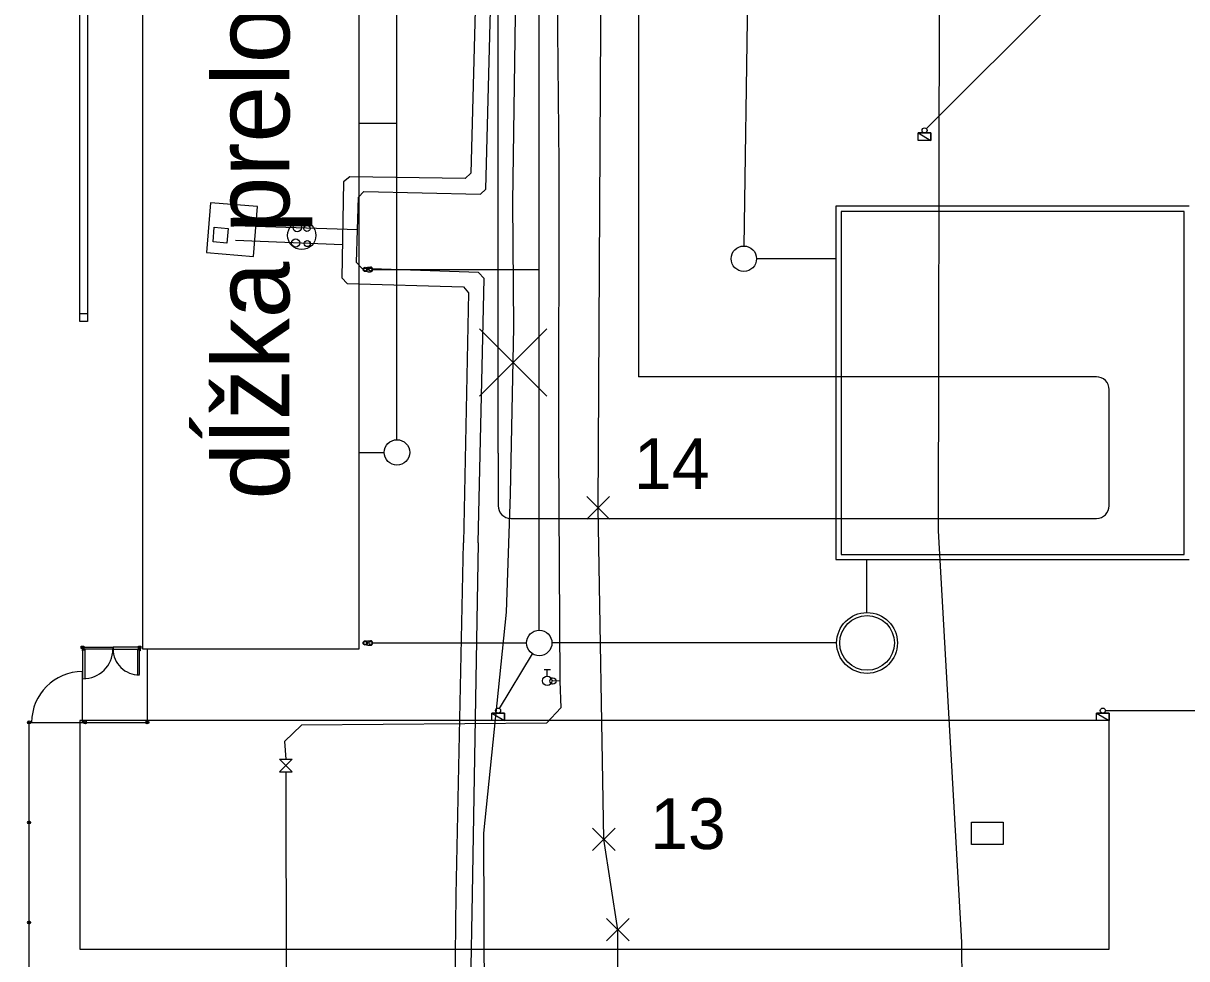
# Model space of a CAD drawing. Extents: x -264095 to -263675, y -1242370 to -1242073.
# Drawn here: x -263972.3 to -263926.53, y -1242264.36 to -1242227.54 of the extents above; entities that cross this region are included whole.
import ezdxf

# ---------------------------------------------------------------- set-up
doc = ezdxf.new("R2010")
doc.units = 0
for name, color, linetype in [('BODY', 7, 'Continuous'), ('KFA_2D_JESTVUJUCE_IS_DSP', 7, 'Continuous'), ('KFA_2D_SITUACIA_DSP', 7, 'Continuous'), ('ORANGE_KABEL_NOVA_TRASA', 7, 'Continuous'), ('POPIS', 7, 'Continuous'), ('Pripojka_NN_pre_ORANGE_vysielac_povodna_trasa', 7, 'Continuous')]:
    doc.layers.add(name, color=color, linetype=linetype)

msp = doc.modelspace()

# ---------------------------------------------------------------- linework, layer by layer
at = {"layer": 'BODY'}
for p, q in [((-263950.126, -1242247.056), (-263949.242, -1242246.172)), ((-263949.242, -1242247.056), (-263950.126, -1242246.172)), ((-263949.901, -1242260.101), (-263949.017, -1242259.217)), ((-263949.017, -1242260.101), (-263949.901, -1242259.217)), ((-263949.352, -1242263.66), (-263948.468, -1242262.776)), ((-263948.468, -1242263.66), (-263949.352, -1242262.776))]:
    msp.add_line(p, q, dxfattribs=at)
at = {"layer": 'KFA_2D_JESTVUJUCE_IS_DSP'}
for p, q in [((-263943.946, -1242236.311), (-263943.136, -1242185.245)), ((-263936.242, -1242215.207), (-263936.305, -1242247.518)), ((-263951.356, -1242221.201), (-263951.228, -1242233.09)), ((-263954.451, -1242224.536), (-263954.692, -1242233.447)), ((-263954.106, -1242234.073), (-263953.851, -1242224.476)), ((-263951.228, -1242233.09), (-263951.241, -1242244.319)), ((-263954.692, -1242233.447), (-263954.912, -1242233.658)), ((-263959.696, -1242233.784), (-263959.771, -1242237.559)), ((-263959.451, -1242233.59), (-263959.696, -1242233.784)), ((-263954.912, -1242233.658), (-263959.451, -1242233.59)), ((-263959.189, -1242236.963), (-263959.11, -1242234.394)), ((-263959.11, -1242234.394), (-263958.895, -1242234.164)), ((-263958.895, -1242234.164), (-263954.308, -1242234.275)), ((-263954.308, -1242234.275), (-263954.106, -1242234.073)), ((-263964.927, -1242234.61), (-263965.088, -1242236.571)), ((-263963.078, -1242234.762), (-263964.927, -1242234.61)), ((-263963.239, -1242236.723), (-263963.078, -1242234.762)), ((-263964.833, -1242236.15), (-263964.786, -1242235.573)), ((-263964.786, -1242235.573), (-263964.238, -1242235.618)), ((-263964.238, -1242235.618), (-263964.285, -1242236.195)), ((-263959.149, -1242235.676), (-263963.972, -1242235.519)), ((-263964.285, -1242236.195), (-263964.833, -1242236.15)), ((-263959.745, -1242236.267), (-263963.952, -1242236.1)), ((-263965.088, -1242236.571), (-263963.239, -1242236.723)), ((-263958.966, -1242237.191), (-263959.189, -1242236.963)), ((-263954.387, -1242237.352), (-263958.966, -1242237.191)), ((-263959.771, -1242237.559), (-263959.557, -1242237.791)), ((-263954.408, -1242247.997), (-263954.173, -1242237.595)), ((-263954.173, -1242237.595), (-263954.387, -1242237.352)), ((-263959.557, -1242237.791), (-263954.983, -1242237.917)), ((-263954.983, -1242237.917), (-263954.788, -1242238.153)), ((-263954.788, -1242238.153), (-263954.978, -1242247.991)), ((-263951.241, -1242244.319), (-263951.192, -1242253.436)), ((-263936.305, -1242247.518), (-263935.392, -1242263.705)), ((-263955.264, -1242261.849), (-263954.978, -1242247.991)), ((-263954.408, -1242247.997), (-263954.644, -1242261.82)), ((-263951.562, -1242252.985), (-263951.812, -1242252.985)), ((-263951.687, -1242253.235), (-263951.687, -1242252.985)), ((-263951.192, -1242253.436), (-263951.461, -1242253.427)), ((-263951.192, -1242253.436), (-263951.15, -1242254.486)), ((-263951.15, -1242254.486), (-263951.718, -1242255.083)), ((-263961.355, -1242255.168), (-263962.028, -1242255.805)), ((-263951.718, -1242255.083), (-263961.355, -1242255.168)), ((-263962.028, -1242255.805), (-263961.971, -1242256.501)), ((-263962.221, -1242256.501), (-263961.721, -1242256.501)), ((-263961.721, -1242256.501), (-263962.221, -1242257.001)), ((-263961.721, -1242257.001), (-263962.221, -1242256.501)), ((-263962.221, -1242257.001), (-263961.721, -1242257.001)), ((-263961.971, -1242257.001), (-263961.846, -1242321.299)), ((-263934.994, -1242258.986), (-263933.751, -1242258.986)), ((-263934.994, -1242259.867), (-263934.994, -1242258.986)), ((-263933.751, -1242258.986), (-263933.751, -1242259.867)), ((-263933.751, -1242259.867), (-263934.994, -1242259.867)), ((-263955.442, -1242275.089), (-263955.264, -1242261.849)), ((-263954.644, -1242261.82), (-263954.858, -1242275.059)), ((-263935.392, -1242263.705), (-263934.919, -1242303.408))]:
    msp.add_line(p, q, dxfattribs=at)
for centre, radius in [((-263961.345, -1242235.895), 0.556), ((-263961.522, -1242235.583), 0.164), ((-263961.138, -1242235.62), 0.122), ((-263961.583, -1242236.191), 0.164), ((-263961.128, -1242236.214), 0.122), ((-263951.687, -1242253.423), 0.188), ((-263951.461, -1242253.427), 0.125)]:
    msp.add_circle(centre, radius, dxfattribs=at)
at = {"layer": 'KFA_2D_SITUACIA_DSP'}
for p, q in [((-263948.093, -1242087.901), (-263948.093, -1242241.458)), ((-263953.617, -1242244.458), (-263953.617, -1242093.307)), ((-263957.597, -1242243.932), (-263957.597, -1242193.383)), ((-263967.593, -1242252.182), (-263967.593, -1242197.782)), ((-263967.593, -1242252.182), (-263967.593, -1242197.782)), ((-263959.097, -1242197.782), (-263959.093, -1242252.182)), ((-263959.093, -1242197.782), (-263959.093, -1242252.182)), ((-263970.07, -1242239.282), (-263970.071, -1242210.684)), ((-263969.77, -1242210.682), (-263969.77, -1242239.282)), ((-263936.772, -1242231.691), (-263926.947, -1242221.865)), ((-263952, -1242251.432), (-263952, -1242223.527)), ((-263959.097, -1242231.482), (-263957.597, -1242231.482)), ((-263937.093, -1242231.862), (-263936.593, -1242231.862)), ((-263937.093, -1242232.152), (-263937.093, -1242231.862)), ((-263937.093, -1242231.862), (-263936.593, -1242232.152)), ((-263937.093, -1242231.862), (-263936.593, -1242232.152)), ((-263936.593, -1242231.862), (-263937.093, -1242231.862)), ((-263936.593, -1242232.152), (-263937.093, -1242232.152)), ((-263936.593, -1242231.862), (-263936.593, -1242232.152)), ((-263936.593, -1242232.152), (-263936.593, -1242231.862)), ((-263926.43, -1242234.749), (-263940.33, -1242234.749)), ((-263940.33, -1242234.749), (-263940.33, -1242248.649)), ((-263926.63, -1242234.949), (-263940.13, -1242234.949)), ((-263940.13, -1242234.949), (-263940.13, -1242248.449)), ((-263926.63, -1242248.449), (-263926.63, -1242234.949)), ((-263958.799, -1242237.162), (-263958.762, -1242237.162)), ((-263958.762, -1242237.162), (-263958.742, -1242237.142)), ((-263958.742, -1242237.142), (-263958.637, -1242237.142)), ((-263940.33, -1242236.811), (-263943.454, -1242236.811)), ((-263958.799, -1242237.302), (-263958.762, -1242237.302)), ((-263958.762, -1242237.302), (-263958.742, -1242237.322)), ((-263958.742, -1242237.322), (-263958.637, -1242237.322)), ((-263958.575, -1242237.232), (-263952, -1242237.232)), ((-263969.77, -1242238.982), (-263970.07, -1242238.982)), ((-263969.77, -1242239.282), (-263970.07, -1242239.282)), ((-263930.081, -1242241.458), (-263948.093, -1242241.458)), ((-263929.582, -1242246.53), (-263929.581, -1242241.959)), ((-263959.097, -1242244.432), (-263958.097, -1242244.432)), ((-263953.617, -1242244.458), (-263953.619, -1242246.529)), ((-263953.119, -1242247.03), (-263930.082, -1242247.03)), ((-263940.33, -1242248.649), (-263926.43, -1242248.649)), ((-263940.13, -1242248.449), (-263926.63, -1242248.449)), ((-263939.13, -1242248.649), (-263939.13, -1242250.737)), ((-263958.799, -1242251.862), (-263958.762, -1242251.862)), ((-263958.762, -1242251.862), (-263958.742, -1242251.842)), ((-263958.742, -1242251.842), (-263958.637, -1242251.842)), ((-263970.018, -1242252.152), (-263970.018, -1242252.052)), ((-263970.018, -1242252.052), (-263969.918, -1242252.052)), ((-263969.918, -1242252.152), (-263970.018, -1242252.152)), ((-263970.005, -1242252.14), (-263970.005, -1242252.065)), ((-263970.005, -1242252.065), (-263969.93, -1242252.065)), ((-263969.93, -1242252.14), (-263970.005, -1242252.14)), ((-263969.93, -1242252.14), (-263969.98, -1242252.14)), ((-263969.98, -1242252.14), (-263969.98, -1242252.24)), ((-263969.98, -1242252.24), (-263969.955, -1242252.24)), ((-263969.968, -1242252.152), (-263969.968, -1242252.202)), ((-263969.968, -1242252.202), (-263969.868, -1242252.202)), ((-263969.955, -1242253.327), (-263969.955, -1242252.19)), ((-263969.955, -1242252.19), (-263969.88, -1242252.19)), ((-263969.93, -1242252.065), (-263969.93, -1242252.14)), ((-263969.918, -1242252.052), (-263969.918, -1242252.152)), ((-263969.918, -1242252.102), (-263968.78, -1242252.102)), ((-263969.918, -1242252.177), (-263969.918, -1242252.102)), ((-263968.78, -1242252.177), (-263969.918, -1242252.177)), ((-263969.88, -1242252.19), (-263969.88, -1242253.327)), ((-263969.868, -1242252.202), (-263969.868, -1242252.177)), ((-263968.78, -1242252.102), (-263968.78, -1242252.177)), ((-263967.768, -1242252.102), (-263968.755, -1242252.102)), ((-263968.755, -1242252.102), (-263968.755, -1242252.177)), ((-263968.755, -1242252.177), (-263967.768, -1242252.177)), ((-263967.818, -1242252.202), (-263967.818, -1242252.177)), ((-263967.718, -1242252.202), (-263967.818, -1242252.202)), ((-263967.805, -1242252.19), (-263967.807, -1242253.177)), ((-263967.73, -1242252.19), (-263967.805, -1242252.19)), ((-263967.768, -1242252.152), (-263967.768, -1242252.052)), ((-263967.768, -1242252.052), (-263967.668, -1242252.052)), ((-263967.768, -1242252.177), (-263967.768, -1242252.102)), ((-263967.668, -1242252.152), (-263967.768, -1242252.152)), ((-263967.755, -1242252.14), (-263967.755, -1242252.065)), ((-263967.755, -1242252.065), (-263967.68, -1242252.065)), ((-263967.755, -1242252.14), (-263967.705, -1242252.14)), ((-263967.68, -1242252.14), (-263967.755, -1242252.14)), ((-263967.732, -1242253.177), (-263967.73, -1242252.19)), ((-263967.705, -1242252.24), (-263967.73, -1242252.24)), ((-263967.718, -1242252.152), (-263967.718, -1242252.202)), ((-263967.705, -1242252.14), (-263967.705, -1242252.24)), ((-263967.68, -1242252.065), (-263967.68, -1242252.14)), ((-263967.668, -1242252.052), (-263967.668, -1242252.152)), ((-263959.093, -1242252.182), (-263967.593, -1242252.182)), ((-263959.093, -1242252.182), (-263967.593, -1242252.182)), ((-263967.418, -1242252.182), (-263967.418, -1242255.057)), ((-263958.799, -1242252.002), (-263958.762, -1242252.002)), ((-263958.762, -1242252.002), (-263958.742, -1242252.022)), ((-263958.742, -1242252.022), (-263958.637, -1242252.022)), ((-263958.575, -1242251.932), (-263952.5, -1242251.932)), ((-263940.302, -1242251.932), (-263951.5, -1242251.932)), ((-263953.57, -1242254.506), (-263952.26, -1242252.359)), ((-263969.968, -1242255.057), (-263969.968, -1242253.057)), ((-263929.73, -1242254.592), (-263920.595, -1242254.592)), ((-263972.128, -1242255.057), (-263972.008, -1242255.057)), ((-263972.068, -1242255.117), (-263972.068, -1242254.997)), ((-263972.068, -1242255.057), (-263967.418, -1242255.057)), ((-263972.068, -1242294.432), (-263972.068, -1242255.057)), ((-263969.928, -1242255.057), (-263969.808, -1242255.057)), ((-263969.868, -1242255.117), (-263969.868, -1242254.997)), ((-263967.478, -1242255.057), (-263967.358, -1242255.057)), ((-263967.418, -1242255.117), (-263967.418, -1242254.997)), ((-263953.87, -1242254.692), (-263953.37, -1242254.692)), ((-263953.87, -1242254.982), (-263953.87, -1242254.692)), ((-263953.87, -1242254.692), (-263953.37, -1242254.982)), ((-263953.87, -1242254.692), (-263953.37, -1242254.982)), ((-263953.37, -1242254.692), (-263953.87, -1242254.692)), ((-263953.37, -1242254.982), (-263953.87, -1242254.982)), ((-263953.37, -1242254.692), (-263953.37, -1242254.982)), ((-263953.37, -1242254.982), (-263953.37, -1242254.692)), ((-263930.08, -1242254.692), (-263929.58, -1242254.692)), ((-263930.08, -1242254.982), (-263930.08, -1242254.692)), ((-263930.08, -1242254.692), (-263929.58, -1242254.982)), ((-263930.08, -1242254.692), (-263929.58, -1242254.982)), ((-263929.58, -1242254.692), (-263930.08, -1242254.692)), ((-263929.58, -1242254.982), (-263930.08, -1242254.982)), ((-263929.58, -1242254.692), (-263929.58, -1242254.982)), ((-263929.58, -1242254.982), (-263929.58, -1242254.692)), ((-263972.128, -1242258.995), (-263972.008, -1242258.995)), ((-263972.068, -1242259.055), (-263972.068, -1242258.935)), ((-263972.128, -1242262.932), (-263972.008, -1242262.932)), ((-263972.068, -1242262.992), (-263972.068, -1242262.872))]:
    msp.add_line(p, q, dxfattribs=at)
msp.add_lwpolyline([(-263967.597, -1242197.782), (-263959.097, -1242197.782), (-263959.097, -1242252.182), (-263967.597, -1242252.182)], close=True, dxfattribs=at)
msp.add_lwpolyline([(-263929.58, -1242254.982), (-263970.077, -1242254.982), (-263970.077, -1242263.982), (-263929.58, -1242263.982), (-263929.58, -1242254.982)], dxfattribs=at)
for centre, radius in [((-263936.843, -1242231.762), 0.1), ((-263943.954, -1242236.811), 0.5), ((-263958.847, -1242237.232), 0.085), ((-263958.847, -1242237.232), 0.0625), ((-263958.637, -1242237.232), 0.0625), ((-263957.597, -1242244.432), 0.5), ((-263939.107, -1242251.932), 1.195), ((-263939.107, -1242251.932), 1.075), ((-263958.847, -1242251.932), 0.085), ((-263952, -1242251.932), 0.5), ((-263958.847, -1242251.932), 0.0625), ((-263958.637, -1242251.932), 0.0625), ((-263953.62, -1242254.592), 0.1), ((-263929.83, -1242254.592), 0.1), ((-263972.068, -1242255.057), 0.06), ((-263969.868, -1242255.057), 0.06), ((-263967.418, -1242255.057), 0.06), ((-263972.068, -1242258.995), 0.06), ((-263972.068, -1242262.932), 0.06)]:
    msp.add_circle(centre, radius, dxfattribs=at)
for centre, radius, start, end in [((-263958.637, -1242237.232), 0.09, 270, 90), ((-263930.081, -1242241.958), 0.5, 359.9785, 89.9999), ((-263953.119, -1242246.53), 0.5, 179.9525, 270), ((-263930.082, -1242246.53), 0.5, 270, 359.9785), ((-263958.637, -1242251.932), 0.09, 270, 90), ((-263969.943, -1242252.165), 1.175, 269.3905, 359.3905), ((-263967.743, -1242252.165), 1.025, 180.6095, 270.6095), ((-263969.968, -1242255.057), 2, 90, 180)]:
    msp.add_arc(centre, radius, start, end, dxfattribs=at)
for centre in [(-263969.943, -1242252.165), (-263969.943, -1242252.165), (-263967.743, -1242252.165)]:
    msp.add_ellipse(centre, major_axis=(0, 0.0125), ratio=0.999995, dxfattribs=at)
at = {"layer": 'ORANGE_KABEL_NOVA_TRASA'}
msp.add_lwpolyline([(-264024.488, -1242318.06), (-264024.034, -1242317.042), (-264023.371, -1242316.883), (-264019.944, -1242316.823), (-264007.092, -1242316.551), (-263992.063, -1242316.466), (-263977.145, -1242316.356), (-263964.015, -1242316.054), (-263949.321, -1242315.778), (-263948.851, -1242315.553), (-263948.88, -1242313.336), (-263948.91, -1242263.218), (-263949.459, -1242259.659), (-263949.684, -1242246.614), (-263949.384, -1242192.159), (-263951.107, -1242181.254), (-263952.04, -1242175.201)], dxfattribs=at)
at = {"layer": 'Pripojka_NN_pre_ORANGE_vysielac_povodna_trasa'}
for p, q in [((-263954.355, -1242242.226), (-263951.703, -1242239.574)), ((-263951.703, -1242242.226), (-263954.355, -1242239.574))]:
    msp.add_line(p, q, dxfattribs=at)
msp.add_lwpolyline([(-263954.154, -1242266.219), (-263954.181, -1242259.421), (-263953.291, -1242250.714), (-263953.128, -1242246.081), (-263953.003, -1242239.508), (-263953.042, -1242234.581), (-263952.925, -1242226.293), (-263952.76, -1242218.883), (-263952.574, -1242210.195), (-263952.394, -1242203.456), (-263952.216, -1242194.818), (-263952.122, -1242190.878), (-263951.644, -1242184.248), (-263951.726, -1242181.217), (-263952.029, -1242175.038), (-263951.914, -1242169.082), (-263951.489, -1242164.316), (-263951.418, -1242162.319), (-263951.777, -1242158.32)], dxfattribs=at)

# ---------------------------------------------------------------- texts
at = {"layer": 'BODY'}
for s, p in [('14', (-263948.278, -1242245.879)), ('13', (-263947.638, -1242260.043))]:
    msp.add_text(s, height=2, dxfattribs=at).set_placement(p)
at = {"layer": 'POPIS'}
msp.add_text('dĺžka preložky 265,70 m', height=3, rotation=90, dxfattribs=at).set_placement((-263961.831, -1242246.288))

doc.saveas('drawing.dxf')
